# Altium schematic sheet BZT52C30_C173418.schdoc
size 127 x 101 mm
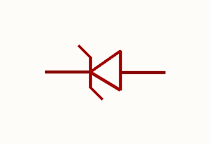
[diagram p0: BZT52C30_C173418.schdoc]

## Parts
D?  bzt52c30_c173418  [SOD-123_L2.7-W1.6-LS3.7-RD]  (value not drawn)

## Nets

Not connected (* = marked no-connect by the designer): D? 1(C) 2(A)

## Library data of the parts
D? = bzt52c30_c173418: 二极管配置:1个独立式;稳压值(标称值):30V;稳压值(范围):28.5V~31.5V;耗散功率(Pd):500mW;; Manufacturer: MDD(辰达半导体); AddInBom: yes; ModelId: ad7e39f9e5534b3c96ffdc5532ebb493; ModelName: SOD-123_L2.7-W1.6-H1.4-LS3.7; ModelTransform: 146.026,62.992,0,180,0,0,0.0005,0,0; Diode Configuration: 1个独立式; Zener Voltage(Nom): 30V; Reverse Leakage Current (Ir): 100nA@23V; Pd - Power Dissipation: 500mW; Impedance(Zzt): 80Ω; Tolerance: ±5%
